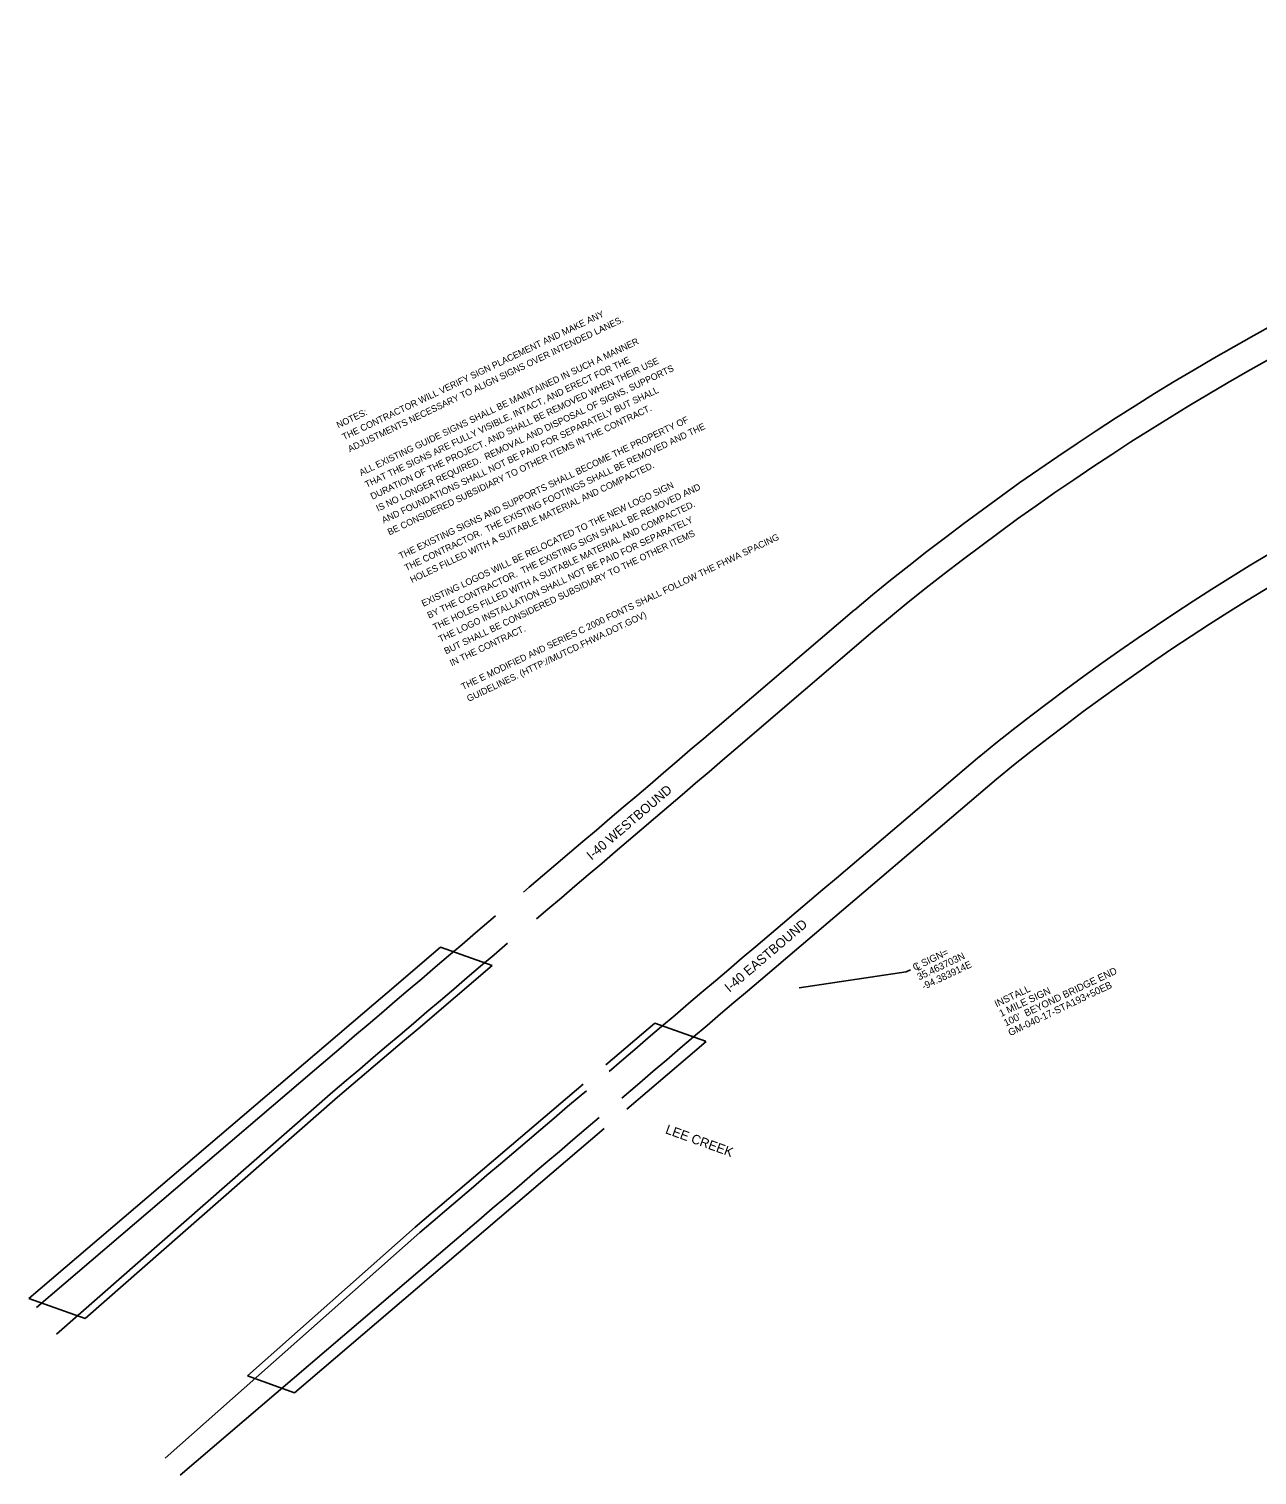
# Model space of a CAD drawing. Extents: x 601881 to 611898, y 415511 to 421131.
# Drawn here: x 601881 to 602925, y 419609 to 420839 of the extents above; entities that cross this region are included whole.
import ezdxf

# ---------------------------------------------------------------- set-up
doc = ezdxf.new("R2010")
doc.units = 0
for name, color, linetype in [('C-ANNO-TEXT', 7, 'Continuous'), ('R_Annotation', 7, 'Continuous'), ('R_Draft', 7, 'Continuous'), ('Scratch_Level_1', 7, 'Continuous')]:
    doc.layers.add(name, color=color, linetype=linetype)

msp = doc.modelspace()

# ---------------------------------------------------------------- linework, layer by layer
at = {"layer": 'C-ANNO-TEXT'}
for p, q in [((602626.3, 420037.2), (602535.5, 420023.6)), ((602630.1, 420039), (602626.3, 420037.2))]:
    msp.add_line(p, q, dxfattribs=at)
at = {"layer": 'R_Draft'}
msp.add_line((602412.6, 419993.6), (602455.7, 419978.3), dxfattribs=at)
for points in [[(602301.1, 420105.1), (602305.9, 420109.2), (602317.3, 420118.9), (602328.7, 420128.6), (602340.2, 420138.3), (602351.6, 420148), (602363, 420157.8), (602374.5, 420167.5), (602385.9, 420177.2), (602397.3, 420186.9), (602408.7, 420196.6), (602420.1, 420206.4), (602431.5, 420216.1), (602442.9, 420225.9), (602454.3, 420235.6), (602465.7, 420245.4), (602582.5, 420345.2)], [(602312, 420082.3), (602321.8, 420090.6), (602333.3, 420100.3), (602344.7, 420110), (602356.1, 420119.7), (602367.6, 420129.4), (602379, 420139.2), (602390.4, 420148.9), (602401.8, 420158.6), (602413.2, 420168.4), (602424.6, 420178.1), (602436, 420187.8), (602447.4, 420197.6), (602458.8, 420207.3), (602470.2, 420217.1), (602481.6, 420226.9), (602598.1, 420326.7)], [(602373.8, 419952.5), (602384.3, 419961.5), (602395.7, 419971.2), (602407.1, 419981), (602418.5, 419990.7), (602429.9, 420000.5), (602441.3, 420010.2), (602452.8, 420019.9), (602464.2, 420029.6), (602475.6, 420039.3), (602487, 420049.1), (602498.5, 420058.8), (602509.9, 420068.5), (602521.3, 420078.2), (602532.8, 420087.9), (602544.2, 420097.6), (602555.6, 420107.3), (602567.1, 420117), (602689, 420220.5)], [(602384.6, 419929.8), (602400, 419943), (602411.4, 419952.8), (602422.9, 419962.5), (602434.3, 419972.3), (602445.7, 419982), (602457.1, 419991.7), (602468.6, 420001.4), (602480, 420011.1), (602491.4, 420020.8), (602502.9, 420030.5), (602514.3, 420040.2), (602525.7, 420049.9), (602537.1, 420059.7), (602548.5, 420069.4), (602560, 420079.1), (602571.4, 420088.8), (602582.8, 420098.6), (602703.3, 420201.2)], [(602371.1, 419958.2), (602412.6, 419993.6)], [(602389, 419920.5), (602440.8, 419964.6), (602456.5, 419978)]]:
    msp.add_lwpolyline(points, dxfattribs=at)
for centre, radius, start, end in [((603991.6, 418658.4), 2197.8, 97.1552, 129.8704), ((603991.6, 418658.4), 2173.8, 97.1552, 129.8704), ((603980, 418636.1), 2043.8, 95.5856, 129.2066), ((603980, 418636.1), 2019.8, 95.4433, 129.2066)]:
    msp.add_arc(centre, radius, start, end, dxfattribs=at)
at = {"layer": 'Scratch_Level_1'}
for p, q in [((602230.6, 420058.2), (602274.5, 420042.6)), ((601880.6, 419759.5), (601928.3, 419742.6)), ((602066.3, 419693.6), (602106.5, 419679.3))]:
    msp.add_line(p, q, dxfattribs=at)
for points in [[(601887.1, 419751.9), (602123.3, 419953.5), (602134.7, 419963.2), (602146.1, 419972.9), (602157.5, 419982.7), (602168.9, 419992.4), (602180.3, 420002.1), (602191.7, 420011.9), (602203.1, 420021.6), (602214.6, 420031.4), (602226, 420041.1), (602237.4, 420050.8), (602248.8, 420060.6), (602260.2, 420070.3), (602271.6, 420080), (602277.3, 420084.9)], [(601880.6, 419759.5), (602173.8, 420009.7), (602185.2, 420019.5), (602230.6, 420058.2)], [(601904, 419729.2), (602139, 419935.1), (602150.4, 419944.8), (602161.8, 419954.5), (602173.3, 419964.3), (602184.7, 419974), (602196.1, 419983.7), (602207.5, 419993.4), (602219, 420003.2), (602230.4, 420012.9), (602241.8, 420022.6), (602253.2, 420032.3), (602264.6, 420042.1), (602276.1, 420051.8), (602287.5, 420061.5)], [(601928.3, 419742.6), (602142.9, 419930.6), (602200, 419979.1), (602211.4, 419988.9), (602274.5, 420042.6)], [(601996.5, 419623.7), (602213, 419815.6), (602224.4, 419825.3), (602235.8, 419835.1), (602247.2, 419844.8), (602258.6, 419854.5), (602270, 419864.3), (602281.5, 419874), (602292.9, 419883.7), (602304.3, 419893.4), (602315.7, 419903.2), (602327.2, 419912.9), (602338.6, 419922.6), (602350, 419932.3), (602354.5, 419936.1)], [(602066.3, 419693.6), (602209.1, 419820.1), (602266.2, 419868.8), (602277.6, 419878.6), (602346.1, 419936.9), (602351.8, 419941.7)], [(602009.2, 419609.3), (602228.9, 419796.9), (602240.3, 419806.7), (602251.7, 419816.4), (602263.1, 419826.2), (602274.5, 419835.9), (602286, 419845.7), (602297.4, 419855.4), (602308.8, 419865.1), (602320.2, 419874.9), (602331.6, 419884.6), (602343, 419894.3), (602354.4, 419904.1), (602365.3, 419913.4)], [(602106.5, 419679.3), (602292.4, 419838), (602303.9, 419847.8), (602369.7, 419904)]]:
    msp.add_lwpolyline(points, dxfattribs=at)

# ---------------------------------------------------------------- texts
at = {"layer": 'R_Annotation'}
for s, height, rotation, p in [('THE CONTRACTOR WILL VERIFY SIGN PLACEMENT AND MAKE ANY', 5.6, 25.4644, (602148.5, 420489.2)), ('ADJUSTMENTS NECESSARY TO ALIGN SIGNS OVER INTENDED LANES.', 5.6, 25.4644, (602153.4, 420479)), ('ALL EXISTING GUIDE SIGNS SHALL BE MAINTAINED IN SUCH A MANNER', 5.6, 25.4644, (602163, 420458.8)), ('THAT THE SIGNS ARE FULLY VISIBLE, INTACT, AND ERECT FOR THE', 5.6, 25.4644, (602167.8, 420448.7)), ('DURATION OF THE PROJECT, AND SHALL BE REMOVED WHEN THEIR USE', 5.6, 25.4644, (602172.6, 420438.6)), ('IS NO LONGER REQUIRED.  REMOVAL AND DISPOSAL OF SIGNS, SUPPORTS', 5.6, 25.4644, (602177.4, 420428.5)), ('AND FOUNDATIONS SHALL NOT BE PAID FOR SEPARATELY BUT SHALL', 5.6, 25.4644, (602182.2, 420418.4)), ('NOTES:', 5.6, 25.4644, (602143.7, 420499.3)), ('BE CONSIDERED SUBSIDIARY TO OTHER ITEMS IN THE CONTRACT.', 5.6, 25.4644, (602187.1, 420408.3)), ('THE EXISTING SIGNS AND SUPPORTS SHALL BECOME THE PROPERTY OF ', 5.6, 25.4644, (602196.7, 420388)), ('THE CONTRACTOR.  THE EXISTING FOOTINGS SHALL BE REMOVED AND THE ', 5.6, 25.4644, (602201.5, 420377.9)), ('HOLES FILLED WITH A SUITABLE MATERIAL AND COMPACTED.', 5.6, 25.4644, (602206.3, 420367.8)), ('EXISTING LOGOS WILL BE RELOCATED TO THE NEW LOGO SIGN', 5.6, 25.4644, (602216, 420347.6)), ('BY THE CONTRACTOR.  THE EXISTING SIGN SHALL BE REMOVED AND ', 5.6, 25.4644, (602220.8, 420337.5)), ('THE HOLES FILLED WITH A SUITABLE MATERIAL AND COMPACTED.', 5.6, 25.4644, (602225.6, 420327.4)), ('THE LOGO INSTALLATION SHALL NOT BE PAID FOR SEPARATELY', 5.6, 25.4644, (602230.4, 420317.3)), ('BUT SHALL BE CONSIDERED SUBSIDIARY TO THE OTHER ITEMS ', 5.6, 25.4644, (602235.2, 420307.1)), ('THE E MODIFIED AND SERIES C 2000 FONTS SHALL FOLLOW THE FHWA SPACING', 5.6, 25.4644, (602249.7, 420276.8)), ('GUIDELINES. (HTTP://MUTCD.FHWA.DOT.GOV)', 5.6, 25.4644, (602254.5, 420266.7)), ('IN THE CONTRACT.', 5.6, 25.4644, (602240, 420297)), ('I-40 WESTBOUND', 8, 40.4644, (602358.9, 420131.8)), ('I-40 EASTBOUND', 8, 40.4644, (602476.2, 420019.5)), ('C SIGN=', 6, 25.4644, (602633.7, 420038)), ('L', 6, 25.4644, (602636.2, 420037.9)), ('35.463703N', 6, 25.4644, (602637.5, 420029.9)), ('-94.383914E', 6, 25.4644, (602641.4, 420021.8)), ("100'  BEYOND BRIDGE END", 6, 25.4644, (602711.1, 419990.7)), ('INSTALL', 6, 25.4644, (602703.3, 420006.9)), ('1 MILE SIGN', 6, 25.4644, (602707.2, 419998.8)), ('GM-040-17-STA193+50EB', 6, 25.4644, (602714.9, 419982.5)), ('LEE CREEK', 8, 340.0839, (602421.1, 419900.1))]:
    msp.add_text(s, height=height, rotation=rotation, dxfattribs=at).set_placement(p)

doc.saveas('drawing.dxf')
